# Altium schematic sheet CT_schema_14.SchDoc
size 144 x 119 mm
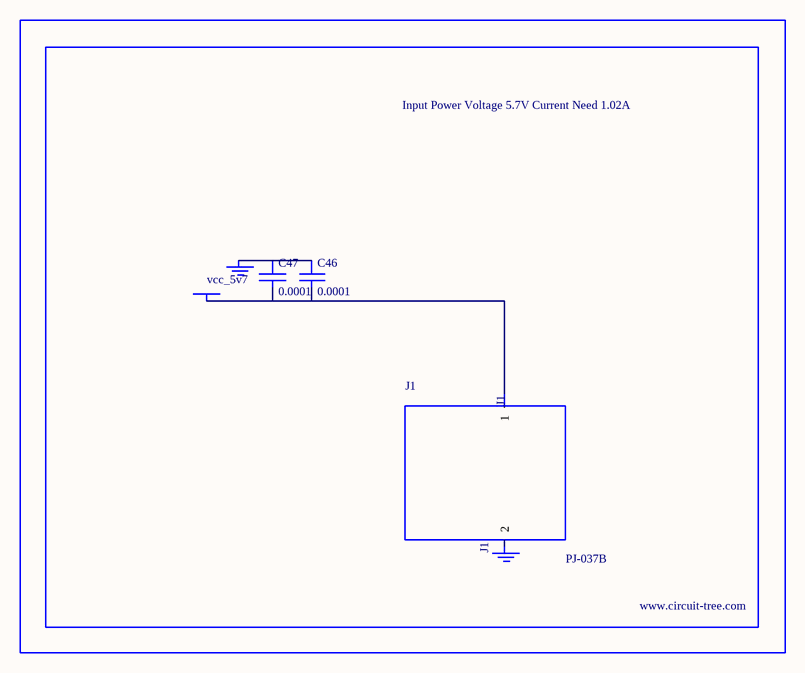
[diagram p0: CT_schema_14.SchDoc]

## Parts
BORDER13  (no value)
C46  0.0001  [EXV-9H]
C47  0.0001  [EXV-9H]
GND_INSTANCE_13_0  (no value)
GND_INSTANCE_13_1  (no value)
J1  PJ-037B  [PJ-037B_PACKAGE]
POWER_INSTANCE_13_0  vcc_5v7

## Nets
NetC46_1: C46.1 C47.1 GND_INSTANCE_13_0.0(GND)
NetC46_2: C46.2 C47.2 J1.1 POWER_INSTANCE_13_0.0(PWR)

Not connected (* = marked no-connect by the designer): GND_INSTANCE_13_1 0(GND); J1 2

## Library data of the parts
BORDER13 = BORDER_PAGE13
C46 C47 = EDK107M035A9HAA
GND_INSTANCE_13_0 GND_INSTANCE_13_1 = GND
POWER_INSTANCE_13_0 = PWR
